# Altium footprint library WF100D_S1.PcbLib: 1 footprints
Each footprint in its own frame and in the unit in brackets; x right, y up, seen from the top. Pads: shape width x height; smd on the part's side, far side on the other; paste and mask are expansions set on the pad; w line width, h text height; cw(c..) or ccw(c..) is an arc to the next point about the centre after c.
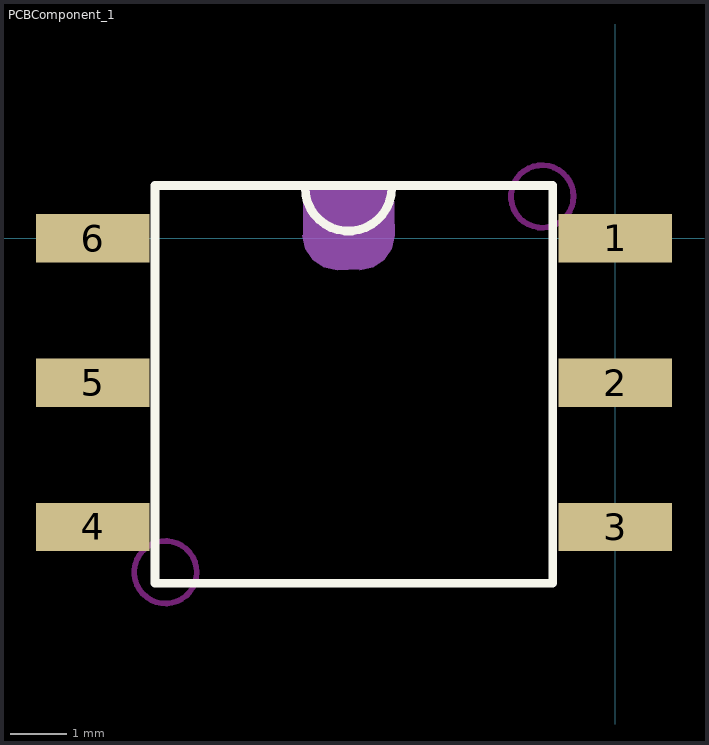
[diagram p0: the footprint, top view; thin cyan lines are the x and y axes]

## PCBComponent_1 [mm]
pads (6):
  rect 2x0.85 smd: 1(0,0) 2(0,-2.54) 3(0,-5.08) 4(-9.2,-5.08) 5(-9.2,-2.54) 6(-9.2,0)
Top Overlay:
  lines w0.152: -5.461,0.889 ccw(c-4.699,0.889) -3.937,0.889 ; -8.103,-6.071 -8.103,0.929 -1.103,0.929 -1.103,-6.071 -8.103,-6.071
Keep-Out Layer:
  circle w0.1: c-7.918,-5.878 r0.55
  circle w0.1: c-1.287,0.737 r0.55
Mechanical 15:
  region: -3.897,0.852 -3.885,0.052 -3.931,-0.183 -4.064,-0.381 -4.262,-0.514 -4.497,-0.56 -4.497,-0.548 -4.897,-0.56 -5.131,-0.514 -5.329,-0.381 -5.462,-0.183 -5.508,0.052 -5.497,0.052 -5.497,0.852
